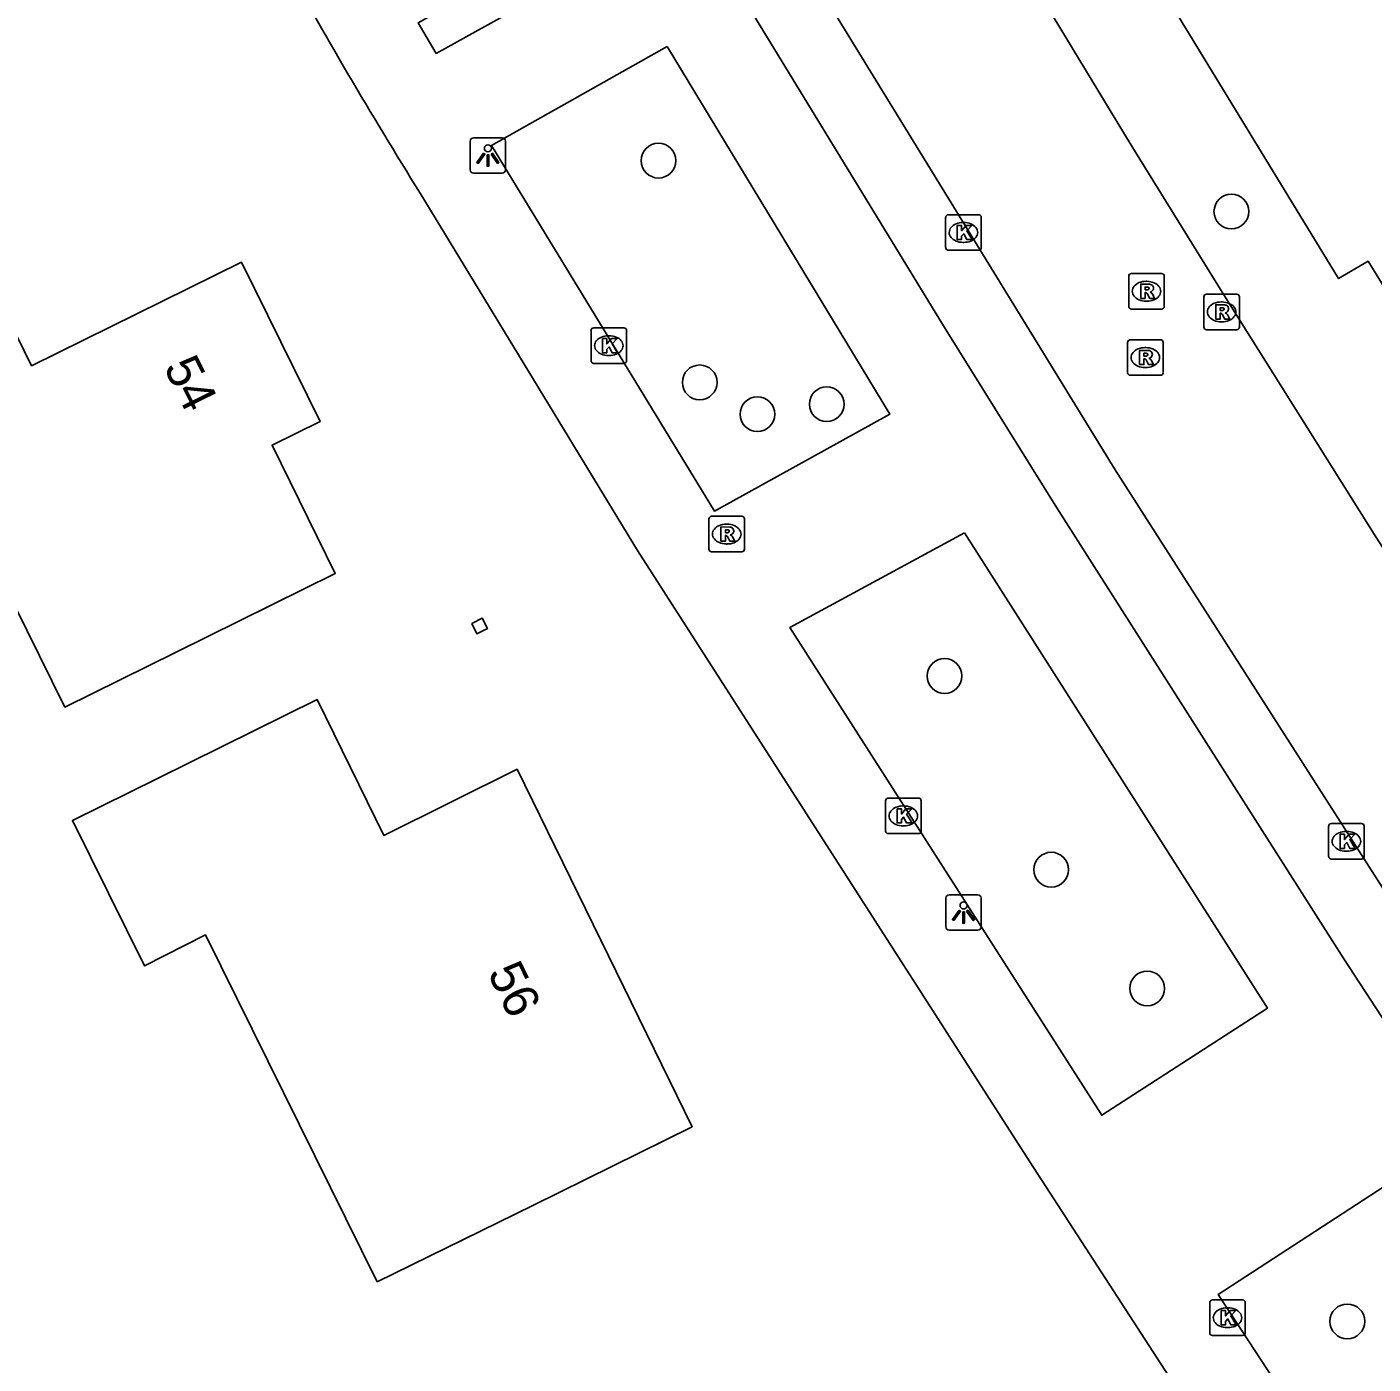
# Model space of a CAD drawing. Extents: x 157793 to 159380, y 380882 to 382313.
# Drawn here: x 158151.07 to 158188.98, y 381464.87 to 381502.51 of the extents above; entities that cross this region are included whole.
import ezdxf

# ---------------------------------------------------------------- set-up
doc = ezdxf.new("R2010")
doc.units = 0
for name, color, linetype in [('IMGEO_Boom', 7, 'Continuous'), ('IMGEO_Kolk', 7, 'Continuous'), ('IMGEO_Lichtpunt', 7, 'Continuous'), ('IMGEO_Pand', 7, 'Continuous'), ('IMGEO_Pand_nummerreeks', 7, 'Continuous'), ('IMGEO_Rijbaan_lokaal_open', 7, 'Continuous'), ('IMGEO_Rioolput', 7, 'Continuous'), ('IMGEO_Voetpad_open', 7, 'Continuous')]:
    doc.layers.add(name, color=color, linetype=linetype)

msp = doc.modelspace()

# ---------------------------------------------------------------- linework, layer by layer
at = {"layer": 'IMGEO_Boom'}
for centre in [(158168.855, 381498.749), (158184.986, 381497.315), (158170.017, 381492.507), (158173.593, 381491.893), (158171.641, 381491.611), (158176.911, 381484.24), (158179.914, 381478.787), (158182.617, 381475.445), (158188.251, 381466.07)]:
    msp.add_circle(centre, 0.489, dxfattribs=at)
at = {"layer": 'IMGEO_Kolk'}
for p, q in [((158176.942, 381496.301), (158176.942, 381497.153)), ((158177.017, 381497.227), (158177.869, 381497.227)), ((158177.43, 381497.007), (158177.455, 381497.007)), ((158177.943, 381497.153), (158177.943, 381496.301)), ((158177.869, 381496.227), (158177.017, 381496.227)), ((158177.453, 381496.447), (158177.428, 381496.447)), ((158166.958, 381493.115), (158166.958, 381493.967)), ((158167.033, 381494.041), (158167.885, 381494.041)), ((158167.959, 381493.967), (158167.959, 381493.115)), ((158167.446, 381493.821), (158167.471, 381493.821)), ((158167.469, 381493.261), (158167.444, 381493.261)), ((158167.885, 381493.041), (158167.033, 381493.041)), ((158175.251, 381479.876), (158175.251, 381480.728)), ((158175.326, 381480.802), (158176.178, 381480.802)), ((158176.252, 381480.728), (158176.252, 381479.876)), ((158175.739, 381480.582), (158175.764, 381480.582)), ((158175.762, 381480.022), (158175.737, 381480.022)), ((158187.725, 381479.16), (158187.725, 381480.012)), ((158187.8, 381480.086), (158188.652, 381480.086)), ((158188.213, 381479.866), (158188.238, 381479.866)), ((158188.726, 381480.012), (158188.726, 381479.16)), ((158176.178, 381479.802), (158175.326, 381479.802)), ((158188.236, 381479.306), (158188.211, 381479.306)), ((158188.652, 381479.086), (158187.8, 381479.086)), ((158184.377, 381465.747), (158184.377, 381466.599)), ((158184.452, 381466.673), (158185.304, 381466.673)), ((158185.378, 381466.599), (158185.378, 381465.747)), ((158184.865, 381466.453), (158184.89, 381466.453)), ((158184.888, 381465.893), (158184.863, 381465.893)), ((158185.304, 381465.673), (158184.452, 381465.673))]:
    msp.add_line(p, q, dxfattribs=at)
for points in [[(158176.942, 381496.301), (158176.942, 381497.153)], [(158177.017, 381497.227), (158177.869, 381497.227)], [(158177.263, 381496.927), (158177.386, 381496.927), (158177.386, 381496.776), (158177.516, 381496.927), (158177.68, 381496.927), (158177.534, 381496.776), (158177.687, 381496.527), (158177.535, 381496.527), (158177.45, 381496.691), (158177.386, 381496.624), (158177.386, 381496.527), (158177.263, 381496.527), (158177.263, 381496.927)], [(158177.943, 381497.153), (158177.943, 381496.301)], [(158177.869, 381496.227), (158177.017, 381496.227)], [(158166.958, 381493.115), (158166.958, 381493.967)], [(158167.033, 381494.041), (158167.885, 381494.041)], [(158167.959, 381493.967), (158167.959, 381493.115)], [(158167.279, 381493.741), (158167.402, 381493.741), (158167.402, 381493.59), (158167.532, 381493.741), (158167.696, 381493.741), (158167.55, 381493.59), (158167.703, 381493.341), (158167.551, 381493.341), (158167.466, 381493.505), (158167.402, 381493.438), (158167.402, 381493.341), (158167.279, 381493.341), (158167.279, 381493.741)], [(158167.885, 381493.041), (158167.033, 381493.041)], [(158175.251, 381479.876), (158175.251, 381480.728)], [(158175.326, 381480.802), (158176.178, 381480.802)], [(158176.252, 381480.728), (158176.252, 381479.876)], [(158175.572, 381480.502), (158175.695, 381480.502), (158175.695, 381480.351), (158175.825, 381480.502), (158175.989, 381480.502), (158175.843, 381480.351), (158175.996, 381480.102), (158175.844, 381480.102), (158175.759, 381480.266), (158175.695, 381480.199), (158175.695, 381480.102), (158175.572, 381480.102), (158175.572, 381480.502)], [(158187.725, 381479.16), (158187.725, 381480.012)], [(158187.8, 381480.086), (158188.652, 381480.086)], [(158188.726, 381480.012), (158188.726, 381479.16)], [(158176.178, 381479.802), (158175.326, 381479.802)], [(158188.046, 381479.786), (158188.169, 381479.786), (158188.169, 381479.635), (158188.299, 381479.786), (158188.463, 381479.786), (158188.317, 381479.635), (158188.47, 381479.386), (158188.318, 381479.386), (158188.233, 381479.55), (158188.169, 381479.483), (158188.169, 381479.386), (158188.046, 381479.386), (158188.046, 381479.786)], [(158188.652, 381479.086), (158187.8, 381479.086)], [(158184.377, 381465.747), (158184.377, 381466.599)], [(158184.452, 381466.673), (158185.304, 381466.673)], [(158185.378, 381466.599), (158185.378, 381465.747)], [(158184.698, 381466.373), (158184.821, 381466.373), (158184.821, 381466.222), (158184.951, 381466.373), (158185.115, 381466.373), (158184.969, 381466.222), (158185.122, 381465.973), (158184.97, 381465.973), (158184.885, 381466.137), (158184.821, 381466.07), (158184.821, 381465.973), (158184.698, 381465.973), (158184.698, 381466.373)], [(158185.304, 381465.673), (158184.452, 381465.673)]]:
    msp.add_lwpolyline(points, dxfattribs=at)
for centre, start, end in [((158177.019, 381497.151), 91.552, 178.448), ((158177.019, 381497.151), 91.552, 178.448), ((158177.867, 381497.151), 1.552, 88.448), ((158177.867, 381497.151), 1.552, 88.448), ((158177.019, 381496.303), 181.552, 268.448), ((158177.019, 381496.303), 181.552, 268.448), ((158177.867, 381496.303), 271.552, 358.448), ((158177.867, 381496.303), 271.552, 358.448), ((158167.035, 381493.965), 91.552, 178.448), ((158167.035, 381493.965), 91.552, 178.448), ((158167.883, 381493.965), 1.552, 88.448), ((158167.883, 381493.965), 1.552, 88.448), ((158167.035, 381493.117), 181.552, 268.448), ((158167.035, 381493.117), 181.552, 268.448), ((158167.883, 381493.117), 271.552, 358.448), ((158167.883, 381493.117), 271.552, 358.448), ((158175.328, 381480.726), 91.552, 178.448), ((158175.328, 381480.726), 91.552, 178.448), ((158176.176, 381480.726), 1.552, 88.448), ((158176.176, 381480.726), 1.552, 88.448), ((158175.328, 381479.878), 181.552, 268.448), ((158175.328, 381479.878), 181.552, 268.448), ((158176.176, 381479.878), 271.552, 358.448), ((158176.176, 381479.878), 271.552, 358.448), ((158187.802, 381480.01), 91.552, 178.448), ((158187.802, 381480.01), 91.552, 178.448), ((158188.65, 381480.01), 1.552, 88.448), ((158188.65, 381480.01), 1.552, 88.448), ((158187.802, 381479.162), 181.552, 268.448), ((158187.802, 381479.162), 181.552, 268.448), ((158188.65, 381479.162), 271.552, 358.448), ((158188.65, 381479.162), 271.552, 358.448), ((158184.454, 381466.597), 91.552, 178.448), ((158184.454, 381466.597), 91.552, 178.448), ((158185.302, 381466.597), 1.552, 88.448), ((158185.302, 381466.597), 1.552, 88.448), ((158184.454, 381465.749), 181.552, 268.448), ((158184.454, 381465.749), 181.552, 268.448), ((158185.302, 381465.749), 271.552, 358.448), ((158185.302, 381465.749), 271.552, 358.448)]:
    msp.add_arc(centre, 0.0765, start, end, dxfattribs=at)
for centre, major_axis, ratio, start_param, end_param in [((158177.429, 381496.727), (-0.387, 0.002), 0.722429, 4.712389, 7.853982), ((158177.454, 381496.727), (-0.39, 0.002), 0.717154, 1.570796, 4.712389), ((158167.445, 381493.541), (-0.387, 0.002), 0.722429, 4.712389, 7.853982), ((158167.47, 381493.541), (-0.39, 0.002), 0.717154, 1.570796, 4.712389), ((158175.738, 381480.302), (-0.387, 0.002), 0.722429, 4.712389, 7.853982), ((158175.763, 381480.302), (-0.39, 0.002), 0.717154, 1.570796, 4.712389), ((158188.212, 381479.586), (-0.387, 0.002), 0.722429, 4.712389, 7.853982), ((158188.237, 381479.586), (-0.39, 0.002), 0.717154, 1.570796, 4.712389), ((158184.864, 381466.173), (-0.387, 0.002), 0.722429, 4.712389, 7.853982), ((158184.889, 381466.173), (-0.39, 0.002), 0.717154, 1.570796, 4.712389)]:
    msp.add_ellipse(centre, major_axis=major_axis, ratio=ratio, start_param=start_param, end_param=end_param, dxfattribs=at)
at = {"layer": 'IMGEO_Lichtpunt'}
for p, q in [((158163.555, 381499.299), (158163.555, 381498.492)), ((158163.555, 381499.299), (158163.555, 381498.492)), ((158164.457, 381499.394), (158163.649, 381499.394)), ((158164.457, 381499.394), (158163.649, 381499.394)), ((158164.551, 381498.492), (158164.551, 381499.299)), ((158164.551, 381498.492), (158164.551, 381499.299)), ((158163.649, 381498.398), (158164.457, 381498.398)), ((158163.649, 381498.398), (158164.457, 381498.398)), ((158176.947, 381477.983), (158176.947, 381477.176)), ((158176.947, 381477.983), (158176.947, 381477.176)), ((158177.849, 381478.078), (158177.041, 381478.078)), ((158177.849, 381478.078), (158177.041, 381478.078)), ((158177.943, 381477.176), (158177.943, 381477.983)), ((158177.943, 381477.176), (158177.943, 381477.983)), ((158177.041, 381477.082), (158177.849, 381477.082)), ((158177.041, 381477.082), (158177.849, 381477.082))]:
    msp.add_line(p, q, dxfattribs=at)
for points in [[(158163.929, 381498.963), (158163.968, 381498.935), (158163.78, 381498.673), (158163.742, 381498.7), (158163.929, 381498.963)], [(158164.031, 381498.915), (158164.078, 381498.915), (158164.078, 381498.593), (158164.031, 381498.593), (158164.031, 381498.915)], [(158164.141, 381498.935), (158164.179, 381498.962), (158164.366, 381498.7), (158164.327, 381498.672), (158164.141, 381498.935)], [(158177.321, 381477.647), (158177.36, 381477.619), (158177.172, 381477.357), (158177.134, 381477.384), (158177.321, 381477.647)], [(158177.423, 381477.599), (158177.47, 381477.599), (158177.47, 381477.277), (158177.423, 381477.277), (158177.423, 381477.599)], [(158177.533, 381477.619), (158177.571, 381477.646), (158177.758, 381477.384), (158177.719, 381477.356), (158177.533, 381477.619)]]:
    msp.add_lwpolyline(points, dxfattribs=at)
for centre in [(158164.054, 381499.097), (158177.446, 381477.781)]:
    msp.add_circle(centre, 0.0994, dxfattribs=at)
for centre, start, end in [((158163.649, 381499.299), 90, 180), ((158163.649, 381499.299), 90, 180), ((158164.457, 381499.299), 0, 90), ((158164.457, 381499.299), 0, 90), ((158163.649, 381498.492), 180, 270), ((158163.649, 381498.492), 180, 270), ((158164.457, 381498.492), 270, 0), ((158164.457, 381498.492), 270, 360), ((158177.041, 381477.983), 90, 180), ((158177.041, 381477.983), 90, 180), ((158177.849, 381477.983), 0, 90), ((158177.849, 381477.983), 0, 90), ((158177.041, 381477.176), 180, 270), ((158177.041, 381477.176), 180, 270), ((158177.849, 381477.176), 270, 0), ((158177.849, 381477.176), 270, 360)]:
    msp.add_arc(centre, 0.0946, start, end, dxfattribs=at)
at = {"layer": 'IMGEO_Pand'}
for points in [[(158150.358, 381486.974), (158149.006, 381486.306), (158148.329, 381487.677), (158146.075, 381486.564), (158143.205, 381492.34), (158145.4, 381493.431), (158149.877, 381495.655), (158151.207, 381492.977), (158157.113, 381495.892), (158159.329, 381491.402), (158157.977, 381490.735), (158159.757, 381487.128), (158155.274, 381484.915), (158152.138, 381483.367), (158150.358, 381486.974)], [(158163.599, 381485.721), (158163.895, 381485.867), (158164.038, 381485.575), (158163.742, 381485.43), (158163.599, 381485.721)], [(158160.936, 381467.185), (158156.099, 381476.949), (158154.388, 381476.077), (158152.358, 381480.171), (158154.767, 381481.361), (158159.25, 381483.574), (158161.126, 381479.751), (158164.877, 381481.614), (158169.804, 381471.551), (158165.323, 381469.334), (158160.936, 381467.185)]]:
    msp.add_lwpolyline(points, dxfattribs=at)
at = {"layer": 'IMGEO_Rijbaan_lokaal_open'}
for points in [[(158161.594, 381534.598), (158163.996, 381530.272), (158165.872, 381526.867), (158169.218, 381520.936), (158171.659, 381516.762), (158175.691, 381509.903), (158178.499, 381505.249), (158182.168, 381499.189), (158184.727, 381495.042), (158189.052, 381488.161), (158192.482, 381482.833), (158196.908, 381476.029), (158199.88, 381471.47), (158203.651, 381465.824), (158207.189, 381460.583), (158211.139, 381454.855), (158219.673, 381442.728)], [(158157.089, 381532.018), (158162.831, 381521.68), (158168.753, 381511.382), (158173.283, 381503.774), (158181.714, 381490.043), (158189.837, 381477.355), (158198.314, 381464.433), (158206.462, 381452.438), (158211.021, 381445.909)]]:
    msp.add_lwpolyline(points, dxfattribs=at)
at = {"layer": 'IMGEO_Rioolput'}
for p, q in [((158182.096, 381494.646), (158182.096, 381495.498)), ((158182.171, 381495.572), (158183.023, 381495.572)), ((158183.097, 381495.498), (158183.097, 381494.646)), ((158182.584, 381495.352), (158182.609, 381495.352)), ((158182.607, 381494.792), (158182.582, 381494.792)), ((158184.211, 381494.064), (158184.211, 381494.916)), ((158184.286, 381494.99), (158185.138, 381494.99)), ((158184.699, 381494.77), (158184.724, 381494.77)), ((158185.212, 381494.916), (158185.212, 381494.064)), ((158183.023, 381494.572), (158182.171, 381494.572)), ((158185.138, 381493.99), (158184.286, 381493.99)), ((158184.722, 381494.21), (158184.697, 381494.21)), ((158182.064, 381492.78), (158182.064, 381493.632)), ((158182.139, 381493.706), (158182.991, 381493.706)), ((158183.065, 381493.632), (158183.065, 381492.78)), ((158182.552, 381493.486), (158182.577, 381493.486)), ((158182.575, 381492.926), (158182.55, 381492.926)), ((158182.991, 381492.706), (158182.139, 381492.706)), ((158170.278, 381487.81), (158170.278, 381488.662)), ((158170.353, 381488.736), (158171.205, 381488.736)), ((158171.279, 381488.662), (158171.279, 381487.81)), ((158170.766, 381488.516), (158170.791, 381488.516)), ((158170.789, 381487.956), (158170.764, 381487.956)), ((158171.205, 381487.736), (158170.353, 381487.736))]:
    msp.add_line(p, q, dxfattribs=at)
for points in [[(158182.096, 381494.646), (158182.096, 381495.498)], [(158182.171, 381495.572), (158183.023, 381495.572)], [(158183.097, 381495.498), (158183.097, 381494.646)], [(158182.685, 381495.27), (158182.433, 381495.272), (158182.433, 381494.872)], [(158182.433, 381494.872), (158182.557, 381494.872), (158182.557, 381495.034), (158182.568, 381495.034)], [(158182.611, 381495.191), (158182.557, 381495.191), (158182.557, 381495.11)], [(158182.557, 381495.11), (158182.609, 381495.11)], [(158182.615, 381495.005), (158182.686, 381494.872), (158182.826, 381494.872), (158182.761, 381494.998)], [(158184.211, 381494.064), (158184.211, 381494.916)], [(158184.286, 381494.99), (158185.138, 381494.99)], [(158184.8, 381494.688), (158184.548, 381494.69), (158184.548, 381494.29)], [(158185.212, 381494.916), (158185.212, 381494.064)], [(158183.023, 381494.572), (158182.171, 381494.572)], [(158184.548, 381494.29), (158184.672, 381494.29), (158184.672, 381494.452), (158184.683, 381494.452)], [(158184.726, 381494.609), (158184.672, 381494.609), (158184.672, 381494.528)], [(158184.672, 381494.528), (158184.724, 381494.528)], [(158184.73, 381494.423), (158184.801, 381494.29), (158184.941, 381494.29), (158184.876, 381494.416)], [(158185.138, 381493.99), (158184.286, 381493.99)], [(158182.064, 381492.78), (158182.064, 381493.632)], [(158182.139, 381493.706), (158182.991, 381493.706)], [(158183.065, 381493.632), (158183.065, 381492.78)], [(158182.653, 381493.404), (158182.401, 381493.406), (158182.401, 381493.006)], [(158182.401, 381493.006), (158182.525, 381493.006), (158182.525, 381493.168), (158182.536, 381493.168)], [(158182.579, 381493.325), (158182.525, 381493.325), (158182.525, 381493.244)], [(158182.525, 381493.244), (158182.577, 381493.244)], [(158182.583, 381493.139), (158182.654, 381493.006), (158182.794, 381493.006), (158182.729, 381493.132)], [(158182.991, 381492.706), (158182.139, 381492.706)], [(158170.278, 381487.81), (158170.278, 381488.662)], [(158170.353, 381488.736), (158171.205, 381488.736)], [(158171.279, 381488.662), (158171.279, 381487.81)], [(158170.867, 381488.434), (158170.615, 381488.436), (158170.615, 381488.036)], [(158170.615, 381488.036), (158170.739, 381488.036), (158170.739, 381488.198), (158170.75, 381488.198)], [(158170.793, 381488.355), (158170.739, 381488.355), (158170.739, 381488.274)], [(158170.739, 381488.274), (158170.791, 381488.274)], [(158170.797, 381488.169), (158170.868, 381488.036), (158171.008, 381488.036), (158170.943, 381488.162)], [(158171.205, 381487.736), (158170.353, 381487.736)]]:
    msp.add_lwpolyline(points, dxfattribs=at)
for centre, radius, start, end in [((158182.173, 381495.496), 0.0765, 91.552, 178.448), ((158182.173, 381495.496), 0.0765, 91.552, 178.448), ((158183.021, 381495.496), 0.0765, 1.552, 88.448), ((158183.021, 381495.496), 0.0765, 1.552, 88.448), ((158182.567, 381494.981), 0.0533, 26.0293, 88.6989), ((158182.593, 381495.299), 0.19, 274.7715, 282.9687), ((158182.617, 381495.095), 0.0964, 77.0061, 93.1865), ((158182.631, 381495.152), 0.0378, 276.6634, 79.6772), ((158182.684, 381495.16), 0.109, 350.3612, 89.416), ((158182.682, 381495.16), 0.112, 277.5842, 350.9817), ((158182.666, 381494.945), 0.108, 29.5134, 73.7905), ((158182.173, 381494.648), 0.0765, 181.552, 268.448), ((158182.173, 381494.648), 0.0765, 181.552, 268.448), ((158183.021, 381494.648), 0.0765, 271.552, 358.448), ((158183.021, 381494.648), 0.0765, 271.552, 358.448), ((158184.288, 381494.914), 0.0765, 91.552, 178.448), ((158184.288, 381494.914), 0.0765, 91.552, 178.448), ((158184.799, 381494.578), 0.109, 350.3612, 89.416), ((158185.136, 381494.914), 0.0765, 1.552, 88.448), ((158185.136, 381494.914), 0.0765, 1.552, 88.448), ((158184.682, 381494.399), 0.0533, 26.0293, 88.6989), ((158184.708, 381494.717), 0.19, 274.7715, 282.9687), ((158184.732, 381494.513), 0.0964, 77.0061, 93.1865), ((158184.746, 381494.57), 0.0378, 276.6634, 79.6772), ((158184.797, 381494.578), 0.112, 277.5842, 350.9817), ((158184.781, 381494.363), 0.108, 29.5134, 73.7905), ((158184.288, 381494.066), 0.0765, 181.552, 268.448), ((158184.288, 381494.066), 0.0765, 181.552, 268.448), ((158185.136, 381494.066), 0.0765, 271.552, 358.448), ((158185.136, 381494.066), 0.0765, 271.552, 358.448), ((158182.141, 381493.63), 0.0765, 91.552, 178.448), ((158182.141, 381493.63), 0.0765, 91.552, 178.448), ((158182.989, 381493.63), 0.0765, 1.552, 88.448), ((158182.989, 381493.63), 0.0765, 1.552, 88.448), ((158182.535, 381493.115), 0.0533, 26.0293, 88.6989), ((158182.561, 381493.433), 0.19, 274.7715, 282.9687), ((158182.585, 381493.229), 0.0964, 77.0061, 93.1865), ((158182.599, 381493.286), 0.0378, 276.6634, 79.6772), ((158182.652, 381493.294), 0.109, 350.3612, 89.416), ((158182.65, 381493.294), 0.112, 277.5842, 350.9817), ((158182.634, 381493.079), 0.108, 29.5134, 73.7905), ((158182.141, 381492.782), 0.0765, 181.552, 268.448), ((158182.141, 381492.782), 0.0765, 181.552, 268.448), ((158182.989, 381492.782), 0.0765, 271.552, 358.448), ((158182.989, 381492.782), 0.0765, 271.552, 358.448), ((158170.355, 381488.66), 0.0765, 91.552, 178.448), ((158170.355, 381488.66), 0.0765, 91.552, 178.448), ((158171.203, 381488.66), 0.0765, 1.552, 88.448), ((158171.203, 381488.66), 0.0765, 1.552, 88.448), ((158170.749, 381488.145), 0.0533, 26.0293, 88.6989), ((158170.775, 381488.463), 0.19, 274.7715, 282.9687), ((158170.799, 381488.259), 0.0964, 77.0061, 93.1865), ((158170.813, 381488.316), 0.0378, 276.6634, 79.6772), ((158170.866, 381488.324), 0.109, 350.3612, 89.416), ((158170.864, 381488.324), 0.112, 277.5842, 350.9817), ((158170.848, 381488.109), 0.108, 29.5134, 73.7905), ((158170.355, 381487.812), 0.0765, 181.552, 268.448), ((158170.355, 381487.812), 0.0765, 181.552, 268.448), ((158171.203, 381487.812), 0.0765, 271.552, 358.448), ((158171.203, 381487.812), 0.0765, 271.552, 358.448)]:
    msp.add_arc(centre, radius, start, end, dxfattribs=at)
for centre, major_axis, ratio, start_param, end_param in [((158182.583, 381495.072), (-0.387, 0.002), 0.722429, 4.712389, 7.853982), ((158182.608, 381495.072), (-0.39, 0.002), 0.717154, 1.570796, 4.712389), ((158184.698, 381494.49), (-0.387, 0.002), 0.722429, 4.712389, 7.853982), ((158184.723, 381494.49), (-0.39, 0.002), 0.717154, 1.570796, 4.712389), ((158182.551, 381493.206), (-0.387, 0.002), 0.722429, 4.712389, 7.853982), ((158182.576, 381493.206), (-0.39, 0.002), 0.717154, 1.570796, 4.712389), ((158170.765, 381488.236), (-0.387, 0.002), 0.722429, 4.712389, 7.853982), ((158170.79, 381488.236), (-0.39, 0.002), 0.717154, 1.570796, 4.712389)]:
    msp.add_ellipse(centre, major_axis=major_axis, ratio=ratio, start_param=start_param, end_param=end_param, dxfattribs=at)
at = {"layer": 'IMGEO_Voetpad_open'}
for points in [[(158207.708, 381447.175), (158196.6, 381463.411), (158191.493, 381471.166), (158188.156, 381476.274), (158180.068, 381488.973), (158176.956, 381493.981), (158171.612, 381502.714), (158167.051, 381510.356), (158163.584, 381516.344), (158161.1, 381520.669), (158154.693, 381532.233), (158152.339, 381536.528), (158148.449, 381543.56)], [(158167.525, 381531.567), (158170.58, 381525.991), (158169.99, 381525.655), (158181.083, 381506.764), (158188.007, 381495.43), (158188.833, 381495.915), (158191.096, 381492.237), (158190.7, 381492.013), (158193.532, 381487.602)], [(158167.536, 381504.519), (158167.416, 381504.728), (158167.03, 381505.399), (158162.095, 381502.632), (158162.598, 381501.769), (158167.536, 381504.519)], [(158169.104, 381501.962), (158165.082, 381499.7), (158164.153, 381499.178), (158170.433, 381488.881), (158175.374, 381491.614), (158169.104, 381501.962)], [(158196.197, 381444.89), (158187.383, 381458.121), (158179.308, 381470.565), (158168.261, 381487.773), (158162.146, 381497.834)], [(158177.476, 381488.273), (158172.552, 381485.604), (158181.337, 381471.872), (158186.001, 381474.885), (158177.476, 381488.273)], [(158189.292, 381469.869), (158184.614, 381466.823), (158191.129, 381456.883), (158198.958, 381445.276), (158200.372, 381442.689), (158206.681, 381444.18), (158201.324, 381451.912), (158189.292, 381469.869)]]:
    msp.add_lwpolyline(points, dxfattribs=at)
msp.add_arc((158288.992, 381576.923), 149.482, 208.93467, 211.94387, dxfattribs=at)

# ---------------------------------------------------------------- texts
at = {"layer": 'IMGEO_Pand_nummerreeks'}
for s, rotation, p in [('54', 296.2682, (158154.913, 381492.937)), ('56', 296.0871, (158164.031, 381475.882))]:
    msp.add_text(s, height=1, rotation=rotation, dxfattribs=at).set_placement(p)

doc.saveas('drawing.dxf')
